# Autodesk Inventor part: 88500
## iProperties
Created: 2007-10
Part Number: 88500
Material: 3.2315.71 AlMgSi1 F28
Document SubType Name: Modellieren
Designer: TMT
Manufacturer: Standard
Standards Organization: Custom
Density: 1 g/cm^3
Description: Pratzen DN 10-50KF
Vendor: LEYBOLD
Author: TMT
Comments: LEYBOLD
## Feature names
1. Extrusion2
2. Extrusion3
3. Extrusion4
4. Extrusion5
5. Extrusion6
6. Extrusion7
